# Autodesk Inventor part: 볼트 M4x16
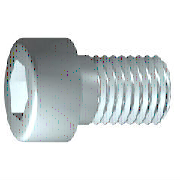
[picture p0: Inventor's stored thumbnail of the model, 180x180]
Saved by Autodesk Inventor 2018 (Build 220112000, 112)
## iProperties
IsCustomPart: 1
Created: 2012-02
Part Number: 볼트 M4x16
Material: 강철, 연강
Description: 6각머리 태핑 나사
Document SubType Name: Modeling
Standard: KS B 1003
Designer: mduedu
Standards Organization: KS
Language: ko-KR
Size Designation: M 4 x 16
Categories: <MemberInstance><Categories><Category DisplayName="조임쇠" InternalName="e4da775c-781d-43d5-af7c-5136215cf5a6" Mnemonic="FSTN"><Category DisplayName="볼트" InternalN
Density: 1 g/cm^3
Appearance: 강철
Author: mduedu
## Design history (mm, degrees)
sketch "스케치1"
  geometry: L1 (-1, 0)-(16, 0); L2 (16, 0)-(16, 2); L3 (16, 2)-(1.75, 2); L4 (1.75, 2)-(1.32, 2); L5 (1.32, 2)-(0, 2); L6 (0, 2)-(0, 3.5); L7 (0, 3.5)-(-4, 3.5); L8 (-4, 3.5)-(-4, 1.732); L9 (-4, 1.732)-(-2, 1.732); L10 (-2, 1.732)-(-1, 0); L11 (-8, 0)-(20, 0) reference; L12 (0, -0.7)-(0, 4.2) reference; L13 (1.75, 2)-(0, 2)
  constraints: 22 end point, 6 parallel, 2 collinear, 2 perpendicular, 1 horizontal, 1 point on line
  dimensions: "d1" = 14.25 distance from line of L3.end L2 (= GEL); "d2" = 0.42952 distance of L4.end L3.end (computed from GAL); "d3" = 4 distance between parallel lines of L8 L6 (= KOH); "d4" = 2 distance of L8.end L9.end (= INTI); "d5" = 60 deg angle of L10 L1; "d6" = 4 diameter of L3 L1 (= GD); "d7" = 4 diameter of L5 L1 (= BDM); "d8" = 3.4641 diameter of L9 L1 (= 1.1547 x SW); "d9" = 7 diameter of L7 L1 (= KOD); "d26" = 16 distance between parallel lines of L12 L2 (= NLG)
revolve "본체" sketch "스케치1" stored, may be unused: angle "d10" = 90 deg
sketch "스케치2"
  geometry: L1 (0, -4.9)-(0, 4.9) reference; L2 (-4.9, 0)-(4.9, 0) reference; L3 (1.732, 0)-(0.866, -1.5); L4 (0.866, -1.5)-(-0.866, -1.5); L5 (-0.866, -1.5)-(-1.732, 0); L6 (-1.732, 0)-(-0.866, 1.5); L7 (-0.866, 1.5)-(0.866, 1.5); L8 (0.866, 1.5)-(1.732, 0); 2 further points
  constraints: 12 end point, 1 coincident, 1 horizontal alignment, 1 point on line, 12 other
extrude "슬롯" join sketch "스케치2" stored distance "d11" = 10; taper "d12" = 0 deg
workplane "Work Plane1"
fillet "Fillet2" dims "d30" = 0.1 (= R)
body "Solid1"
fillet "모깎기1" dims "d17" = 0.4 (= RR)
feature "스레드" dims "d13" = 14.25 (= GEL), "d14" = 0
chamfer "모따기1" distance "d15" = 0.42941 (= -0.5 x SPD + 0.5 x GD); stored, may be unused: second distance "d16" = 0.42941 (= GUL), angle "d27" = 45 deg
other parameters: "GD" = 4 (= NND) [user parameter; used in 2 equation terms], "NLG" = 16 [user parameter; used in 1 equation term], "GEL" = 14.25 [user parameter; used in 2 equation terms], "KOD" = 7 [user parameter; used in 1 equation term], "KOH" = 4 [user parameter; used in 1 equation term], "INTI" = 2 [user parameter; used in 1 equation term], "GAL" = 0.42941 (= 0.61345 x PTC) [user parameter; used in 1 equation term], "GUL" = 0.42941 (= 0.61345 x PTC) [user parameter; used in 1 equation term], "BDM" = 4 (= NND) [user parameter; used in 1 equation term], "SW" = 3 [user parameter; used in 2 equation terms], "RR" = 0.4 [user parameter; used in 1 equation term], "SPD" = 3.14117 (= NND - 1.2269 x PTC) [user parameter; used in 1 equation term], "d19" = 0, "d28" = 0, "d29" = 0, "R" = 0.1 [user parameter; used in 1 equation term], "PHH" = 0.2 [user parameter], "GD1" = 3.14117 (= THREADDIA - 1.2269 x PTC) [user parameter], "THREADDIA" = 4 [user parameter; used in 1 equation term], "FAWI" = 45 deg [user parameter], "TPU" = 14.28571 (computed from PTC) [user parameter], "PTC" = 0.7 [user parameter; used in 5 equation terms], "NND" = 4 [user parameter; used in 3 equation terms], "TOA" = 30 deg [user parameter], "E0" = 3.465 (= 1.155 x SW) [user parameter]
